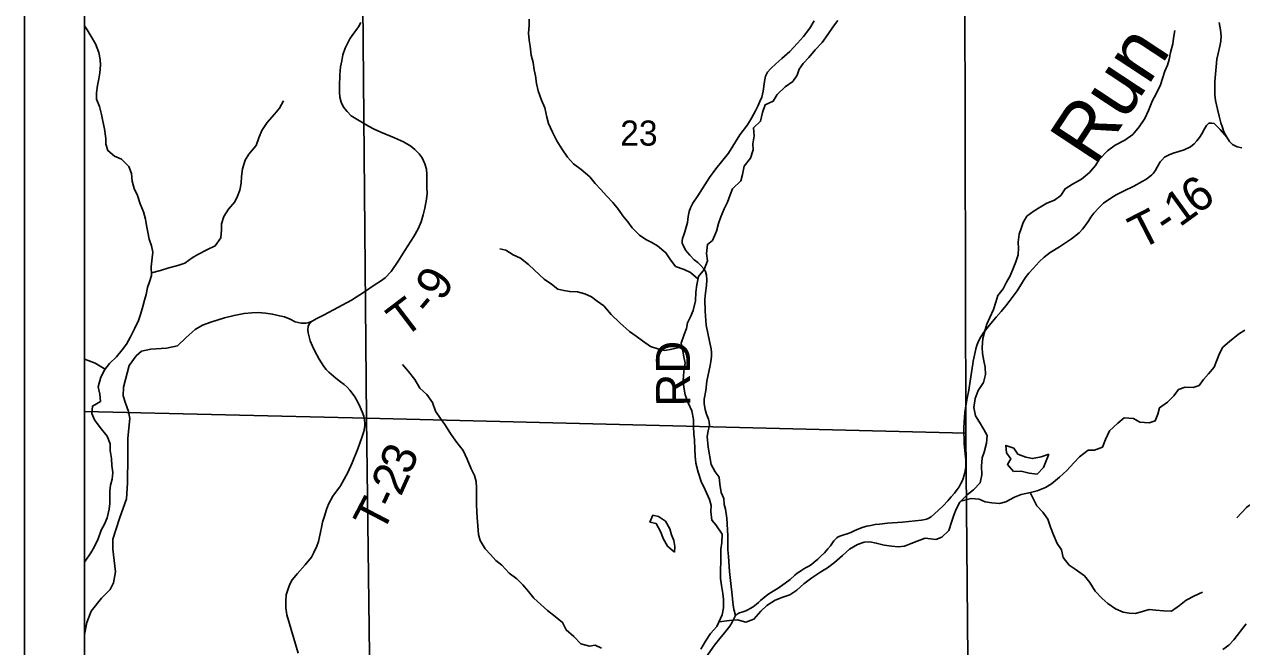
# Model space of a CAD drawing. Extents: x 0 to 34, y 0 to 22.
# Drawn here: x 2 to 4.027, y 15.007 to 16.044 of the extents above; entities that cross this region are included whole.
import ezdxf

# ---------------------------------------------------------------- set-up
doc = ezdxf.new("R2010")
doc.units = 0
for name, color, linetype in [('Default', 7, 'Continuous'), ('GM_X_Minor_Lake', 7, 'Continuous'), ('GM_X_Minor_River', 7, 'Continuous'), ('GM_X_Minor_River_Text', 7, 'Continuous'), ('GM_X_Rail_Line', 7, 'Continuous'), ('GM_X_Section', 7, 'Continuous'), ('GM_X_Section_Text', 7, 'Continuous'), ('GM_X_Township_Road', 7, 'Continuous'), ('GM_X_Township_Road_Text', 7, 'Continuous'), ('SH_Cut_Line', 7, 'Continuous'), ('SH_Data', 7, 'Continuous')]:
    doc.layers.add(name, color=color, linetype=linetype)

msp = doc.modelspace()

# ---------------------------------------------------------------- linework, layer by layer
at = {"layer": 'Default'}
for points in [[(2.1, 16.4038), (2.1, 15.3991), (2.5698, 15.3877), (2.561, 16.3904)], [(2.1, 15.3991), (2.1, 14.393), (2.5826, 14.3817), (2.5698, 15.3877)]]:
    msp.add_lwpolyline(points, close=True, dxfattribs=at)
at = {"layer": 'GM_X_Minor_Lake'}
for points in [[(3.7058, 15.3277), (3.6929, 15.3237), (3.6782, 15.3205), (3.6671, 15.3231), (3.6542, 15.3279), (3.6473, 15.338), (3.6343, 15.3424), (3.6352, 15.3303), (3.6422, 15.3201), (3.637, 15.3106), (3.6436, 15.3031)], [(3.6436, 15.3031), (3.6469, 15.2993), (3.6594, 15.2998), (3.6731, 15.2966), (3.6864, 15.2948), (3.6969, 15.3056), (3.7058, 15.3277)], [(3.0823, 15.1646), (3.083, 15.1741), (3.0811, 15.184), (3.0773, 15.1938), (3.0746, 15.2037), (3.0674, 15.2165), (3.056, 15.2241), (3.0465, 15.2263), (3.0431, 15.2185)], [(3.0431, 15.2185), (3.0416, 15.2149), (3.0518, 15.2123), (3.0598, 15.1979), (3.0636, 15.1877), (3.0705, 15.1748), (3.0823, 15.1646)]]:
    msp.add_lwpolyline(points, dxfattribs=at)
at = {"layer": 'GM_X_Minor_River'}
for points in [[(3.1215, 15.6198), (3.109, 15.6305), (3.0987, 15.6354), (3.0843, 15.6406), (3.0744, 15.6531), (3.068, 15.6633), (3.0543, 15.675), (3.0444, 15.6803), (3.0346, 15.6852), (3.0239, 15.6927), (3.0122, 15.7048), (3.0049, 15.7147), (2.9966, 15.7249), (2.9893, 15.7355), (2.9795, 15.7468), (2.9692, 15.7581), (2.9597, 15.7687), (2.9506, 15.7789), (2.9415, 15.7895), (2.927, 15.802), (2.9145, 15.8114), (2.9042, 15.8224), (2.8947, 15.8364), (2.8864, 15.85), (2.8795, 15.864), (2.8726, 15.8787), (2.8696, 15.8893), (2.8665, 15.9045), (2.8612, 15.9174), (2.8554, 15.9329), (2.8527, 15.9454), (2.8508, 15.9579), (2.8489, 15.9681), (2.847, 15.9802), (2.8439, 15.9923), (2.842, 16.0071), (2.8404, 16.0173), (2.8396, 16.0291), (2.8403, 16.042), (2.8407, 16.0522)], [(2.1, 15.1475), (2.1012, 15.15), (2.1107, 15.1636), (2.1163, 15.1731), (2.1227, 15.1868), (2.128, 15.2012), (2.1332, 15.2115), (2.1378, 15.2217), (2.1411, 15.2361), (2.1422, 15.246), (2.1422, 15.2566), (2.1426, 15.2661), (2.1433, 15.2763), (2.1463, 15.2862), (2.1474, 15.2972), (2.1458, 15.3093), (2.145, 15.3206), (2.1431, 15.3339), (2.1431, 15.3449), (2.1377, 15.3578), (2.126, 15.3725), (2.1168, 15.3854), (2.1123, 15.3956), (2.1134, 15.4081), (2.1266, 15.4157), (2.1254, 15.4278), (2.1231, 15.4403), (2.1276, 15.4563), (2.134, 15.4692), (2.1419, 15.4787), (2.1533, 15.4901), (2.1631, 15.5018), (2.1699, 15.5113), (2.177, 15.5231), (2.1834, 15.5368), (2.1902, 15.5504), (2.1932, 15.5607), (2.197, 15.5739), (2.2, 15.5842), (2.2026, 15.594), (2.2052, 15.6054), (2.2082, 15.6149), (2.2116, 15.6255), (2.2112, 15.6399), (2.2126, 15.6547), (2.2138, 15.6642), (2.2115, 15.6748), (2.208, 15.6858), (2.2057, 15.6979), (2.2034, 15.7089), (2.2019, 15.7195), (2.1984, 15.7316), (2.1927, 15.7448), (2.1885, 15.7588), (2.1831, 15.7702), (2.1793, 15.7823), (2.1785, 15.7952), (2.1739, 15.8069), (2.1618, 15.819), (2.15, 15.8243), (2.139, 15.8334), (2.1356, 15.844), (2.1356, 15.8534), (2.1336, 15.8697), (2.1309, 15.8822), (2.1282, 15.8936), (2.1252, 15.9068), (2.1202, 15.9193), (2.1202, 15.9299), (2.122, 15.9417), (2.1239, 15.9527), (2.1258, 15.9629), (2.1269, 15.9758), (2.1261, 15.9853), (2.1242, 15.997), (2.1184, 16.011), (2.1112, 16.0235), (2.1047, 16.0345), (2.1, 16.0412)], [(3.1457, 15.6836), (3.1526, 15.6991), (3.1559, 15.712), (3.1595, 15.7231), (3.1651, 15.7364), (3.1706, 15.7478), (3.175, 15.76), (3.1791, 15.7696), (3.193, 15.783), (3.1959, 15.7936), (3.1984, 15.8073), (3.2092, 15.8207), (3.2132, 15.8348), (3.2131, 15.8447), (3.2149, 15.8583), (3.214, 15.8712), (3.2256, 15.8827), (3.2288, 15.8968), (3.2332, 15.9094), (3.2468, 15.9156), (3.2535, 15.9267), (3.2666, 15.9397), (3.2794, 15.9486), (3.2869, 15.9589), (3.2902, 15.9688), (3.2965, 15.9783), (3.3063, 15.9887), (3.3164, 16.0013), (3.3284, 16.0132), (3.3377, 16.0266), (3.347, 16.0404), (3.3545, 16.0499)], [(3.906, 15.9854), (3.9082, 15.9968), (3.9118, 16.0112), (3.9132, 16.0207), (3.9153, 16.0337)], [(3.1566, 15.049), (3.174, 15.051), (3.1873, 15.0523), (3.201, 15.0483), (3.2145, 15.053), (3.2261, 15.0664), (3.2363, 15.076), (3.2502, 15.0848), (3.263, 15.0899), (3.2744, 15.0938), (3.286, 15.1015), (3.2977, 15.1119), (3.3108, 15.1223), (3.3259, 15.1323), (3.3372, 15.1385), (3.3488, 15.1477), (3.3619, 15.1593), (3.3736, 15.17), (3.3871, 15.1778), (3.3981, 15.1817), (3.4075, 15.1821), (3.4182, 15.18), (3.4315, 15.1767), (3.4444, 15.1746), (3.455, 15.1739), (3.4653, 15.1748), (3.4766, 15.1791), (3.4864, 15.183), (3.4996, 15.1881), (3.5174, 15.186), (3.5273, 15.1895), (3.5389, 15.201), (3.5444, 15.2166), (3.5477, 15.2265), (3.5514, 15.2361), (3.5573, 15.2479), (3.57, 15.2606), (3.5802, 15.2686), (3.5911, 15.2801), (3.5943, 15.2938), (3.5934, 15.3082), (3.5944, 15.3219), (3.5977, 15.3314), (3.6017, 15.3463), (3.6027, 15.3588), (3.5976, 15.369), (3.5903, 15.3814), (3.5837, 15.392), (3.5809, 15.4056), (3.583, 15.4204), (3.5882, 15.4341), (3.5967, 15.4475), (3.6004, 15.4604), (3.5999, 15.4726), (3.5975, 15.4835), (3.5954, 15.4957), (3.5949, 15.5055), (3.5959, 15.5207), (3.5999, 15.5352), (3.6024, 15.5447), (3.6076, 15.5557), (3.6135, 15.5691), (3.6172, 15.5813), (3.6209, 15.5923), (3.6295, 15.6034), (3.6354, 15.6145), (3.6413, 15.6251), (3.6465, 15.6373), (3.6509, 15.6484), (3.6546, 15.6598), (3.6552, 15.6712), (3.6544, 15.681), (3.6565, 15.6943), (3.6594, 15.7039), (3.6631, 15.7138), (3.669, 15.7241), (3.6811, 15.7329), (3.6912, 15.7391), (3.7025, 15.7457), (3.715, 15.7508), (3.7255, 15.7585), (3.7326, 15.7699), (3.745, 15.7773), (3.7601, 15.7861), (3.7732, 15.7969), (3.7833, 15.8088), (3.7896, 15.8187), (3.8035, 15.8333), (3.8159, 15.8425), (3.8321, 15.8507), (3.8453, 15.8603), (3.8561, 15.8733), (3.8654, 15.8871), (3.8717, 15.9004), (3.878, 15.9168), (3.8839, 15.9267), (3.8917, 15.9427), (3.8946, 15.9534), (3.899, 15.9656), (3.9031, 15.9755), (3.906, 15.9854)], [(2.2115, 15.63), (2.2267, 15.6339), (2.2403, 15.6385), (2.2555, 15.6419), (2.2672, 15.6458), (2.2793, 15.6549), (2.2891, 15.6606), (2.3039, 15.6682), (2.3179, 15.6747), (2.3269, 15.688), (2.3284, 15.702), (2.3284, 15.7115), (2.3321, 15.724), (2.3397, 15.7358), (2.3506, 15.748), (2.3548, 15.7574), (2.3585, 15.7673), (2.3608, 15.7791), (2.3615, 15.7901), (2.3634, 15.8029), (2.3679, 15.8174), (2.3735, 15.8276), (2.386, 15.842), (2.3905, 15.8549), (2.3954, 15.8671), (2.4044, 15.8804), (2.4165, 15.8941), (2.4248, 15.9043), (2.4316, 15.9165)], [(3.0948, 15.5067), (3.0779, 15.503), (3.0665, 15.5007), (3.0563, 15.5026), (3.0427, 15.5075), (3.029, 15.5165), (3.0187, 15.5245), (3.0077, 15.5324), (2.9914, 15.5464), (2.977, 15.5603), (2.9648, 15.5747), (2.9538, 15.583), (2.9443, 15.5898), (2.9329, 15.5951), (2.9208, 15.5981), (2.9079, 15.5988), (2.8981, 15.6007), (2.8882, 15.6029), (2.8776, 15.6108), (2.8654, 15.6195), (2.8495, 15.6346), (2.8396, 15.6437), (2.8263, 15.6543), (2.8138, 15.6599), (2.8016, 15.6674), (2.7918, 15.6701)], [(3.1512, 15.2103), (3.1446, 15.2183), (3.1431, 15.2323), (3.1434, 15.2425), (3.1407, 15.2527), (3.1335, 15.2686), (3.1266, 15.2823), (3.1217, 15.2978), (3.1182, 15.3129), (3.1167, 15.3247), (3.1163, 15.3364), (3.1155, 15.3516), (3.1147, 15.3614), (3.1139, 15.3743), (3.1142, 15.3857), (3.1111, 15.4001), (3.105, 15.4137), (3.1001, 15.4266), (3.0982, 15.4394), (3.097, 15.4497), (3.0973, 15.4591), (3.0984, 15.4698), (3.0999, 15.4796), (3.098, 15.4898), (3.0965, 15.4997), (3.0934, 15.5129), (3.0987, 15.527), (3.1024, 15.5372), (3.1043, 15.5467), (3.1088, 15.5566), (3.1137, 15.5672), (3.1171, 15.5831), (3.1182, 15.5975), (3.1196, 15.6097), (3.1222, 15.6237), (3.1317, 15.6355), (3.1373, 15.6499), (3.1358, 15.662), (3.1372, 15.6773), (3.1457, 15.6836)], [(3.5592, 15.2498), (3.5762, 15.2542), (3.5895, 15.2528), (3.5994, 15.2487), (3.6108, 15.247), (3.6233, 15.246), (3.6339, 15.2484), (3.6486, 15.2565), (3.6595, 15.2608), (3.675, 15.264), (3.6864, 15.2671), (3.6999, 15.2726), (3.7101, 15.2788), (3.7236, 15.2895), (3.7356, 15.3007), (3.7472, 15.3133), (3.7566, 15.3237), (3.7709, 15.3344), (3.7815, 15.3349), (3.7947, 15.3396), (3.7999, 15.3526), (3.8065, 15.3667), (3.8204, 15.3798), (3.8309, 15.3882), (3.8465, 15.3872), (3.8572, 15.3813), (3.8727, 15.3799), (3.8829, 15.3835), (3.8873, 15.3945), (3.8899, 15.4052), (3.9034, 15.4144), (3.9135, 15.4252), (3.9217, 15.4355), (3.9327, 15.4394), (3.946, 15.4392), (3.9558, 15.4423), (3.9633, 15.4523), (3.9715, 15.4618), (3.9808, 15.4726), (3.9845, 15.4828), (3.9897, 15.4954), (3.9952, 15.5061), (4.0065, 15.5157), (4.0212, 15.528), (4.0317, 15.5346)], [(2.1345, 15.4697), (2.1177, 15.4793), (2.1063, 15.4839), (2.1, 15.486)], [(2.9611, 15.0051), (2.9505, 15.01), (2.9407, 15.0085), (2.9267, 15.0122), (2.9149, 15.0243), (2.9023, 15.0353), (2.8962, 15.0478), (2.8837, 15.0576), (2.8708, 15.0674), (2.8598, 15.0776), (2.8484, 15.0882), (2.8393, 15.0995), (2.8298, 15.1101), (2.8199, 15.1203), (2.8074, 15.1297), (2.7952, 15.1429), (2.785, 15.1509), (2.7762, 15.1607), (2.7671, 15.1705), (2.7587, 15.1841), (2.756, 15.1944), (2.7549, 15.2084), (2.7541, 15.2224), (2.7533, 15.2319), (2.7525, 15.244), (2.7525, 15.2539), (2.7528, 15.272), (2.7524, 15.2823), (2.7493, 15.2925), (2.744, 15.3035), (2.7371, 15.3197), (2.7303, 15.3341), (2.7185, 15.3496), (2.7093, 15.3625), (2.7002, 15.3772), (2.6926, 15.3871), (2.6846, 15.3996), (2.6793, 15.4139), (2.6701, 15.4272), (2.6587, 15.4378), (2.65, 15.4525), (2.6393, 15.4657), (2.6298, 15.4775)], [(3.6746, 15.2639), (3.6855, 15.2421), (3.6959, 15.2312), (3.704, 15.2195), (3.7083, 15.2063), (3.7133, 15.1935), (3.7196, 15.1791), (3.7269, 15.1686), (3.7297, 15.1561), (3.7397, 15.1433), (3.7496, 15.1366), (3.7649, 15.1254), (3.7741, 15.1141), (3.783, 15.1001), (3.7942, 15.0877), (3.8037, 15.0791), (3.8167, 15.0705), (3.8293, 15.0646), (3.8392, 15.0632), (3.8498, 15.0626), (3.863, 15.0665), (3.8728, 15.0693), (3.8835, 15.0682), (3.8967, 15.0669), (3.9096, 15.0666), (3.9232, 15.0759), (3.9344, 15.0851), (3.9484, 15.0921), (3.9616, 15.0983)], [(3.153, 15.0412), (3.1618, 15.0603), (3.1639, 15.0721), (3.1641, 15.0858), (3.1629, 15.096), (3.1608, 15.1093), (3.1592, 15.121), (3.159, 15.1358), (3.1593, 15.1479), (3.1595, 15.1597), (3.1598, 15.17), (3.1612, 15.181), (3.1618, 15.1946), (3.1512, 15.2103)], [(3.1263, 15.0033), (3.1338, 15.0166), (3.1421, 15.0295), (3.153, 15.0412)]]:
    msp.add_lwpolyline(points, dxfattribs=at)
at = {"layer": 'GM_X_Rail_Line'}
msp.add_lwpolyline([(2.1, 18.7171), (2.1, 14.1), (4.5781, 14.1), (4.5658, 14.9668), (4.5509, 15.5331), (4.5478, 16.582), (4.5489, 17.6578), (4.5474, 17.7028), (4.5429, 17.9404), (4.5419, 17.9684), (4.5402, 18.2851), (4.5408, 18.3763), (4.5397, 18.3961), (4.5397, 18.4045), (4.5399, 18.4424), (4.5403, 18.5054), (4.5462, 18.6416), (3.8456, 18.6615), (3.8442, 18.6615), (2.9234, 18.6945), (2.9222, 18.6946), (2.7892, 18.6993), (2.7864, 18.6994)], close=True, dxfattribs=at)
at = {"layer": 'GM_X_Section'}
for points in [[(2.561, 16.3904), (3.5651, 16.354), (3.5676, 15.363), (2.5698, 15.3877)], [(2.5698, 15.3877), (3.5676, 15.363), (3.5764, 14.3611), (2.5826, 14.3817)]]:
    msp.add_lwpolyline(points, close=True, dxfattribs=at)
at = {"layer": 'GM_X_Township_Road'}
for points in [[(2.4693, 15.5463), (2.4723, 15.5465), (2.4791, 15.5492), (2.483, 15.5516), (2.4861, 15.5531), (2.4992, 15.5602), (2.5444, 15.5842), (2.5662, 15.5982), (2.5826, 15.6093), (2.593, 15.6161), (2.6006, 15.6218), (2.6107, 15.6324), (2.6221, 15.6491), (2.6335, 15.6672), (2.6486, 15.6905), (2.6554, 15.7031), (2.6606, 15.7147), (2.6642, 15.7265), (2.6667, 15.7376), (2.6695, 15.7524), (2.6704, 15.7621), (2.6703, 15.7725), (2.6701, 15.7943), (2.6693, 15.8028), (2.6669, 15.8116), (2.6622, 15.8213), (2.6575, 15.8282), (2.6502, 15.8352), (2.6432, 15.8406), (2.6313, 15.8479), (2.616, 15.8547), (2.5934, 15.8641), (2.5825, 15.869), (2.5728, 15.874), (2.5439, 15.8912), (2.5372, 15.8986), (2.5315, 15.9059), (2.5274, 15.9142), (2.5255, 15.9222), (2.5249, 15.9305), (2.5249, 15.9406), (2.5254, 15.9599), (2.5266, 15.9731), (2.5284, 15.9832), (2.5305, 15.9932), (2.5341, 16.0041), (2.5393, 16.0141), (2.5421, 16.0196), (2.5457, 16.0251), (2.5564, 16.0395), (2.5601, 16.0469)], [(3.1308, 14.9838), (3.1492, 15.0098), (3.158, 15.021), (3.1658, 15.0307), (3.1744, 15.0415), (3.1782, 15.048), (3.1833, 15.0583), (3.1836, 15.06), (3.1836, 15.0613), (3.1831, 15.0634), (3.1824, 15.0657), (3.1817, 15.0677), (3.1811, 15.0693), (3.1795, 15.081), (3.1783, 15.0932), (3.176, 15.1124), (3.1738, 15.1324), (3.1722, 15.1573), (3.1712, 15.1686), (3.1714, 15.1918), (3.1693, 15.2214), (3.1674, 15.2364), (3.1653, 15.2441), (3.1644, 15.2543), (3.1603, 15.2642), (3.1579, 15.2779), (3.1567, 15.2898), (3.1502, 15.2984), (3.1437, 15.3108), (3.1384, 15.3394), (3.1369, 15.3576), (3.1384, 15.3667), (3.1408, 15.3757), (3.1403, 15.3816), (3.139, 15.3865), (3.1358, 15.3945), (3.1334, 15.4022), (3.132, 15.4119), (3.132, 15.4193), (3.1346, 15.4339), (3.1364, 15.4494), (3.142, 15.4757), (3.1429, 15.4824), (3.144, 15.4904), (3.1441, 15.4971), (3.1434, 15.5036), (3.1414, 15.5132), (3.1349, 15.5429), (3.1334, 15.5659), (3.1331, 15.5855), (3.134, 15.5966), (3.1358, 15.6091), (3.1363, 15.6181), (3.1357, 15.6262), (3.134, 15.6323), (3.1311, 15.6367), (3.1262, 15.6422), (3.121, 15.6469), (3.1154, 15.6518), (3.1078, 15.6594), (3.1039, 15.6639), (3.1012, 15.6673), (3.0988, 15.6711), (3.0967, 15.6759), (3.0954, 15.6792), (3.0952, 15.683), (3.0958, 15.6869), (3.0973, 15.6918), (3.0996, 15.6982), (3.1021, 15.7059), (3.1039, 15.7137), (3.1054, 15.7237), (3.1071, 15.7321), (3.109, 15.7383), (3.1131, 15.7461), (3.1211, 15.7582), (3.1405, 15.7884), (3.1511, 15.8033), (3.1724, 15.8293), (3.1913, 15.8595), (3.2039, 15.8765), (3.2108, 15.8876), (3.217, 15.8999), (3.221, 15.9075), (3.2246, 15.9153), (3.2276, 15.9223), (3.2299, 15.9323), (3.2323, 15.9488), (3.2337, 15.9573), (3.2372, 15.964), (3.2428, 15.9704), (3.2509, 15.9777), (3.2612, 15.9867), (3.2744, 15.9984), (3.2874, 16.0121), (3.2972, 16.0236), (3.3075, 16.0376), (3.3152, 16.0498)], [(3.989, 16.047), (3.9917, 16.0344), (3.9924, 16.0239), (3.9919, 16.0155), (3.9903, 16.0075), (3.9874, 15.9954), (3.9855, 15.9855), (3.9842, 15.9727), (3.9821, 15.9484), (3.9822, 15.9266), (3.9829, 15.9167), (3.9864, 15.9022), (3.9893, 15.8909), (3.992, 15.8799), (3.9945, 15.8717), (3.9971, 15.8647), (4.0018, 15.8557), (4.0062, 15.8486), (4.0112, 15.8436), (4.0194, 15.8398), (4.0267, 15.8382)], [(4.0018, 15.8557), (3.9909, 15.8685), (3.9808, 15.8784), (3.9769, 15.8793), (3.972, 15.879), (3.9679, 15.8752), (3.9648, 15.8699), (3.9604, 15.8613), (3.9566, 15.8553), (3.9522, 15.8495), (3.9476, 15.8448), (3.9413, 15.8396), (3.9307, 15.8346), (3.9219, 15.8317), (3.9127, 15.8291), (3.9058, 15.8264), (3.8984, 15.8226), (3.8935, 15.8178), (3.8911, 15.8146), (3.8858, 15.8058), (3.8826, 15.8), (3.8794, 15.7956), (3.8769, 15.7929), (3.874, 15.7903), (3.8672, 15.7855), (3.8608, 15.7819), (3.8474, 15.7744), (3.8297, 15.7661), (3.8177, 15.7597), (3.8088, 15.7543), (3.7967, 15.7458), (3.7881, 15.7378), (3.7807, 15.7295), (3.7758, 15.7224), (3.7723, 15.7169), (3.7674, 15.7098), (3.7618, 15.7025), (3.7559, 15.6967), (3.7433, 15.6863), (3.7233, 15.6732), (3.708, 15.6639), (3.6978, 15.6559), (3.6895, 15.6481), (3.6793, 15.6372), (3.6726, 15.6296), (3.6665, 15.6214), (3.6527, 15.6), (3.6394, 15.5821), (3.634, 15.575), (3.6261, 15.5656), (3.6178, 15.5559), (3.6091, 15.5456), (3.6023, 15.5372), (3.5976, 15.5309), (3.5926, 15.5235), (3.588, 15.5149), (3.5855, 15.509), (3.5839, 15.5036), (3.5817, 15.4928), (3.5799, 15.4831), (3.579, 15.4782), (3.5769, 15.4637), (3.5749, 15.4497), (3.5723, 15.4346), (3.5698, 15.4213), (3.568, 15.4119), (3.5658, 15.3976), (3.5644, 15.3814), (3.5639, 15.3716), (3.5649, 15.3451), (3.5664, 15.329), (3.567, 15.323), (3.5674, 15.3186), (3.5675, 15.315), (3.5676, 15.3102), (3.5673, 15.3063), (3.5666, 15.3004), (3.5646, 15.2929), (3.5629, 15.2876), (3.5611, 15.2832), (3.5593, 15.2792), (3.5562, 15.2737), (3.5531, 15.2691), (3.5483, 15.2632), (3.5431, 15.2571), (3.5373, 15.25), (3.5297, 15.2419), (3.5222, 15.2347), (3.5154, 15.2285), (3.5096, 15.2235), (3.5045, 15.2206), (3.502, 15.2196), (3.4995, 15.219), (3.4935, 15.218), (3.462, 15.2149), (3.4372, 15.2132), (3.4238, 15.2114), (3.4167, 15.2106), (3.4095, 15.2094), (3.4028, 15.208), (3.3966, 15.2063), (3.3895, 15.2036), (3.3814, 15.2002), (3.3759, 15.1974), (3.37, 15.1952), (3.3645, 15.1935), (3.3596, 15.1922), (3.3549, 15.1905), (3.3525, 15.1888), (3.3509, 15.1872), (3.3479, 15.1838), (3.3456, 15.1805), (3.3419, 15.1752), (3.3379, 15.1702), (3.3322, 15.1639), (3.3266, 15.1586), (3.3208, 15.1531), (3.315, 15.148), (3.3104, 15.1444), (3.3058, 15.1414), (3.3016, 15.1392), (3.2978, 15.1369), (3.2946, 15.135), (3.2921, 15.1331), (3.2869, 15.1296), (3.283, 15.1264), (3.2749, 15.1194), (3.2666, 15.1132), (3.2549, 15.105), (3.2468, 15.1), (3.2397, 15.0953), (3.2353, 15.0922), (3.2317, 15.0893), (3.2258, 15.0842), (3.2223, 15.081), (3.219, 15.0784), (3.2135, 15.074), (3.2084, 15.0707), (3.2047, 15.0687), (3.2012, 15.067), (3.1978, 15.0658), (3.1943, 15.0647), (3.1908, 15.0638), (3.1884, 15.0629), (3.1867, 15.0614), (3.185, 15.06), (3.1833, 15.0583)], [(2.1, 15.0279), (2.1042, 15.0477), (2.111, 15.0667), (2.1286, 15.0881), (2.143, 15.1026), (2.1486, 15.1136), (2.1519, 15.1318), (2.1472, 15.1697), (2.1474, 15.1864), (2.1586, 15.2206), (2.1698, 15.2536), (2.172, 15.2794), (2.1721, 15.3249), (2.1723, 15.3545), (2.1756, 15.3875), (2.1736, 15.3992), (2.1682, 15.4128), (2.1644, 15.4249), (2.1651, 15.4394), (2.1747, 15.4754), (2.1864, 15.4918), (2.195, 15.4994), (2.2106, 15.5029), (2.2367, 15.5046), (2.2548, 15.5085), (2.2696, 15.5221), (2.2843, 15.5357), (2.2967, 15.5429), (2.3102, 15.5478), (2.3332, 15.555), (2.3492, 15.5591), (2.3659, 15.5623), (2.3786, 15.5633), (2.3892, 15.5638), (2.4013, 15.5625), (2.413, 15.5609), (2.4246, 15.5584), (2.4333, 15.5565), (2.4424, 15.5527), (2.4509, 15.5483), (2.4608, 15.5462), (2.4674, 15.5462), (2.4693, 15.5463)], [(2.4791, 15.5492), (2.4744, 15.5444), (2.4724, 15.5406), (2.4719, 15.5352), (2.4725, 15.5299), (2.4761, 15.5167), (2.4797, 15.5079), (2.4837, 15.4995), (2.4909, 15.4862), (2.4986, 15.4737), (2.5023, 15.4687), (2.5068, 15.4645), (2.5188, 15.4545), (2.5265, 15.4484), (2.5322, 15.4439), (2.5373, 15.4398), (2.5421, 15.4344), (2.546, 15.4293), (2.5503, 15.4232), (2.555, 15.4148), (2.5589, 15.4064), (2.5625, 15.3985), (2.5651, 15.3911), (2.5663, 15.3844), (2.5669, 15.3793), (2.5667, 15.3753), (2.5653, 15.3657), (2.562, 15.3556), (2.5553, 15.337), (2.546, 15.3133), (2.5383, 15.2977), (2.5261, 15.2752), (2.5137, 15.2581), (2.5066, 15.2449), (2.5033, 15.236), (2.4992, 15.2232), (2.4965, 15.215), (2.4951, 15.2086), (2.4923, 15.1952), (2.4895, 15.1828), (2.4869, 15.1745), (2.482, 15.1644), (2.478, 15.1563), (2.4674, 15.1436), (2.4547, 15.1291), (2.446, 15.1188), (2.4419, 15.1113), (2.4396, 15.1055), (2.4357, 15.0937), (2.4352, 15.0836), (2.4355, 15.0719), (2.4369, 15.0606), (2.4557, 14.9967)], [(4.0188, 15.2218), (4.0345, 15.2389), (4.0379, 15.2417), (4.0423, 15.2443), (4.0483, 15.2468), (4.0542, 15.2492), (4.062, 15.2517), (4.071, 15.2557), (4.0801, 15.259), (4.0869, 15.2606), (4.0952, 15.2612), (4.1002, 15.2613), (4.1058, 15.2608), (4.1124, 15.2602), (4.1477, 15.2584), (4.1848, 15.2561), (4.2101, 15.254)], [(4.0339, 15.0454), (4.0139, 15.0187), (4.0054, 15.0098), (3.9955, 15.0027)]]:
    msp.add_lwpolyline(points, dxfattribs=at)
at = {"layer": 'SH_Cut_Line'}
msp.add_lwpolyline([(2.1, 20.9), (2.1, 14.1), (4.5781, 14.1)], dxfattribs=at)
at = {"layer": 'SH_Data'}
for p, q in [((2, 21), (2, 14)), ((2.1, 20.9), (2.1, 14.1))]:
    msp.add_line(p, q, dxfattribs=at)

# ---------------------------------------------------------------- texts
at = {"layer": 'GM_X_Minor_River_Text'}
msp.add_text('Run', height=0.09469, rotation=56.6083, dxfattribs=at).set_placement((3.7818, 15.8056))
at = {"layer": 'GM_X_Section_Text'}
msp.add_text('23', height=0.04186, rotation=0, dxfattribs=at).set_placement((2.992, 15.8417))
at = {"layer": 'GM_X_Township_Road_Text'}
for s, height, rotation, p in [('6', 0.0568, 36.0643, (3.9518, 15.7256)), ('1', 0.0568, 35.9207, (3.9233, 15.705)), ('T', 0.0568, 27.1611, (3.858, 15.6677)), ('-', 0.0568, 33.6408, (3.9019, 15.6907)), ('9', 0.0568, 58.4933, (2.696, 15.5806)), ('T', 0.0568, 37.2333, (2.6318, 15.52)), ('-', 0.0568, 50.0732, (2.6757, 15.5553)), ('RD', 0.05682, 90.4937, (3.1088, 15.4073)), ('3', 0.0568, 69.0471, (2.6426, 15.2916)), ('2', 0.0568, 65.7266, (2.6268, 15.2563)), ('-', 0.0568, 64.7936, (2.6165, 15.2343)), ('T', 0.0568, 62.4191, (2.5957, 15.1943))]:
    msp.add_text(s, height=height, rotation=rotation, dxfattribs=at).set_placement(p)

doc.saveas('drawing.dxf')
